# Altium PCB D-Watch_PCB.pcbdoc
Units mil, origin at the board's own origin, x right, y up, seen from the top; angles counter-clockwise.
Board outline 2207.1 x 1974.96 mil, 4 copper layers (Top Layer, Inner1, Inner2, Bottom Layer); 63 components, 57 nets, 260 pads, 83 vias.
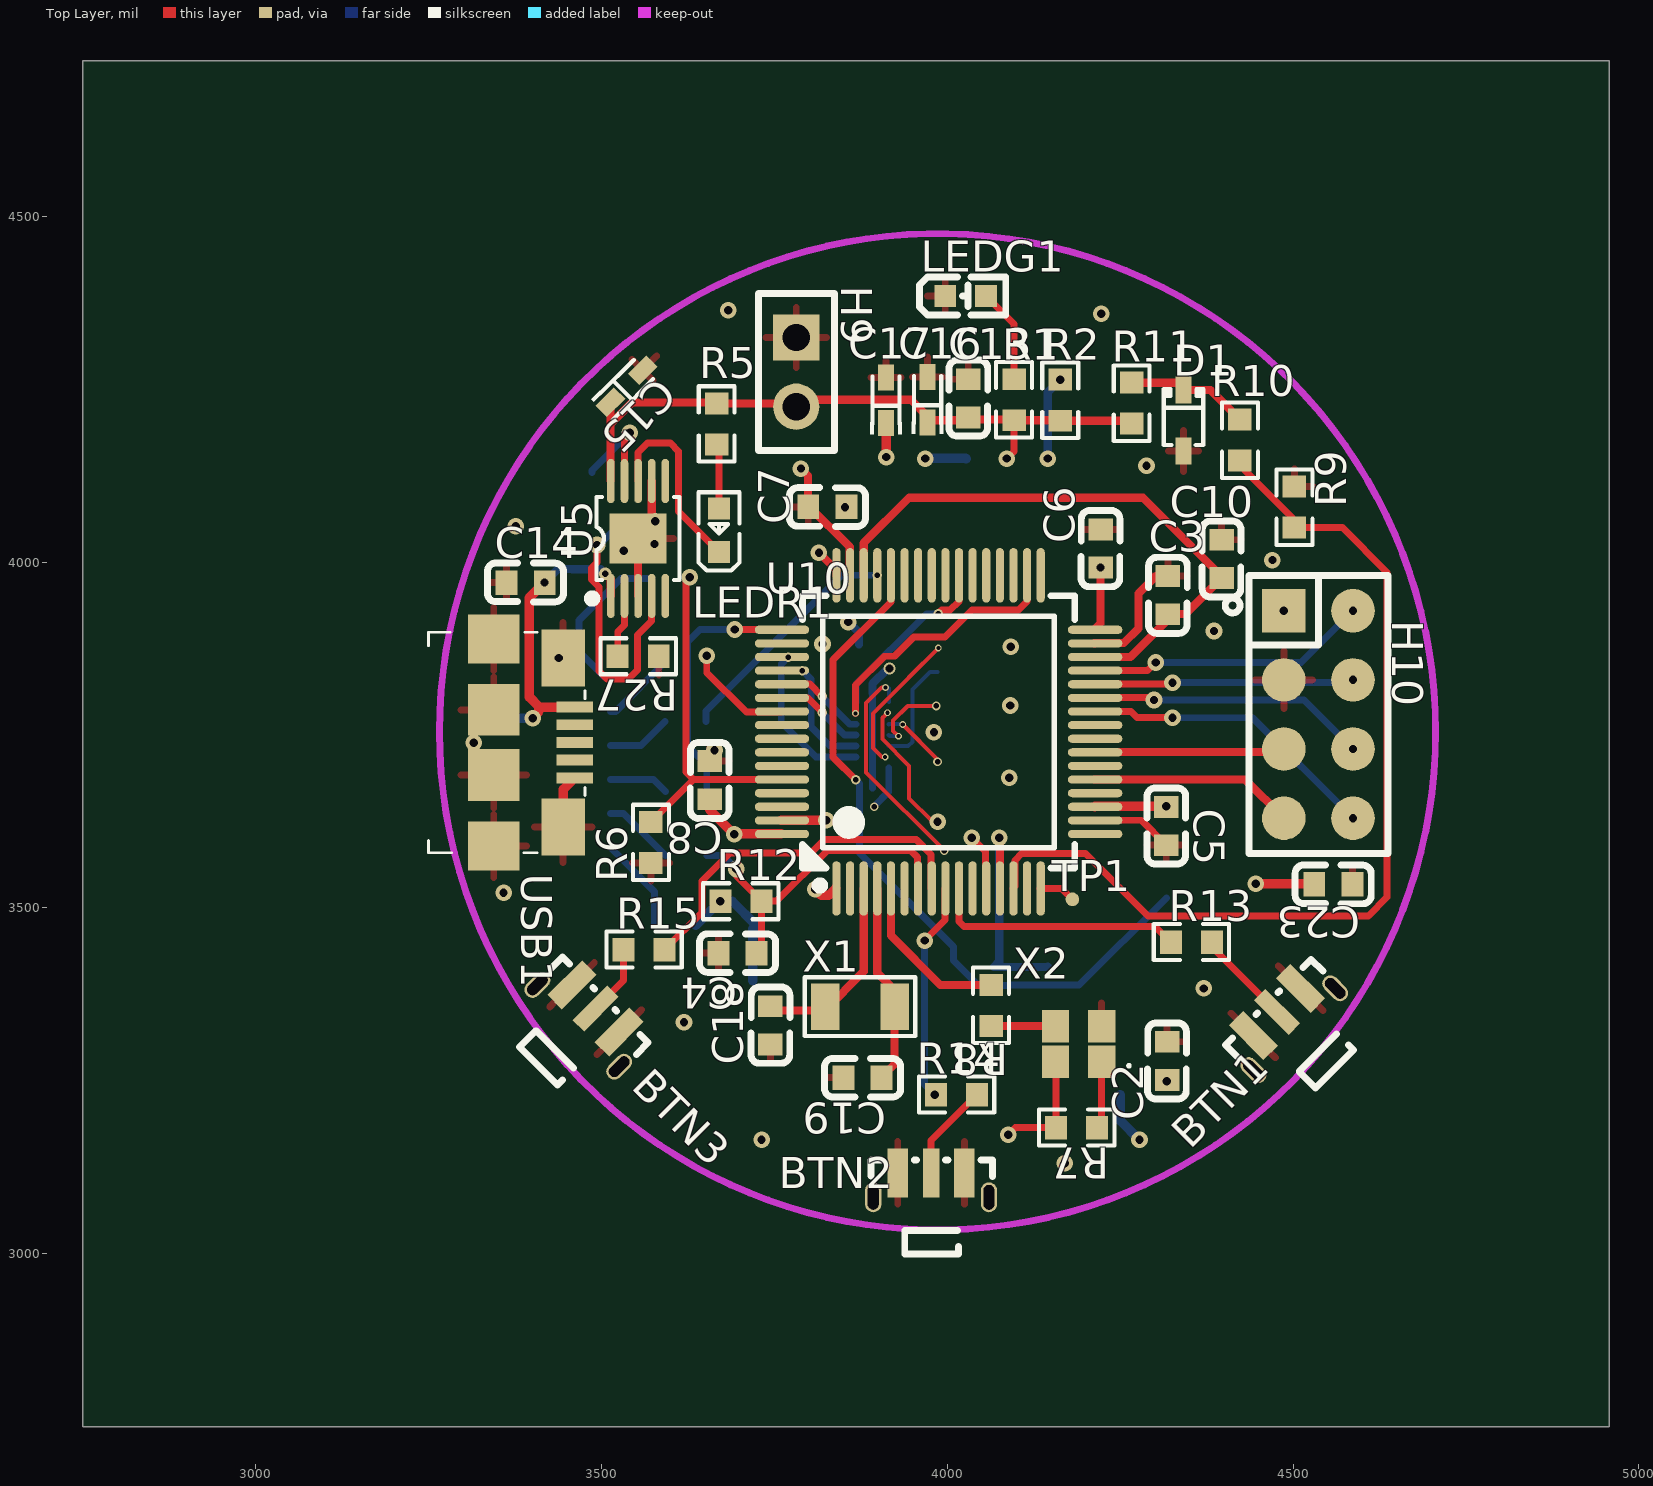
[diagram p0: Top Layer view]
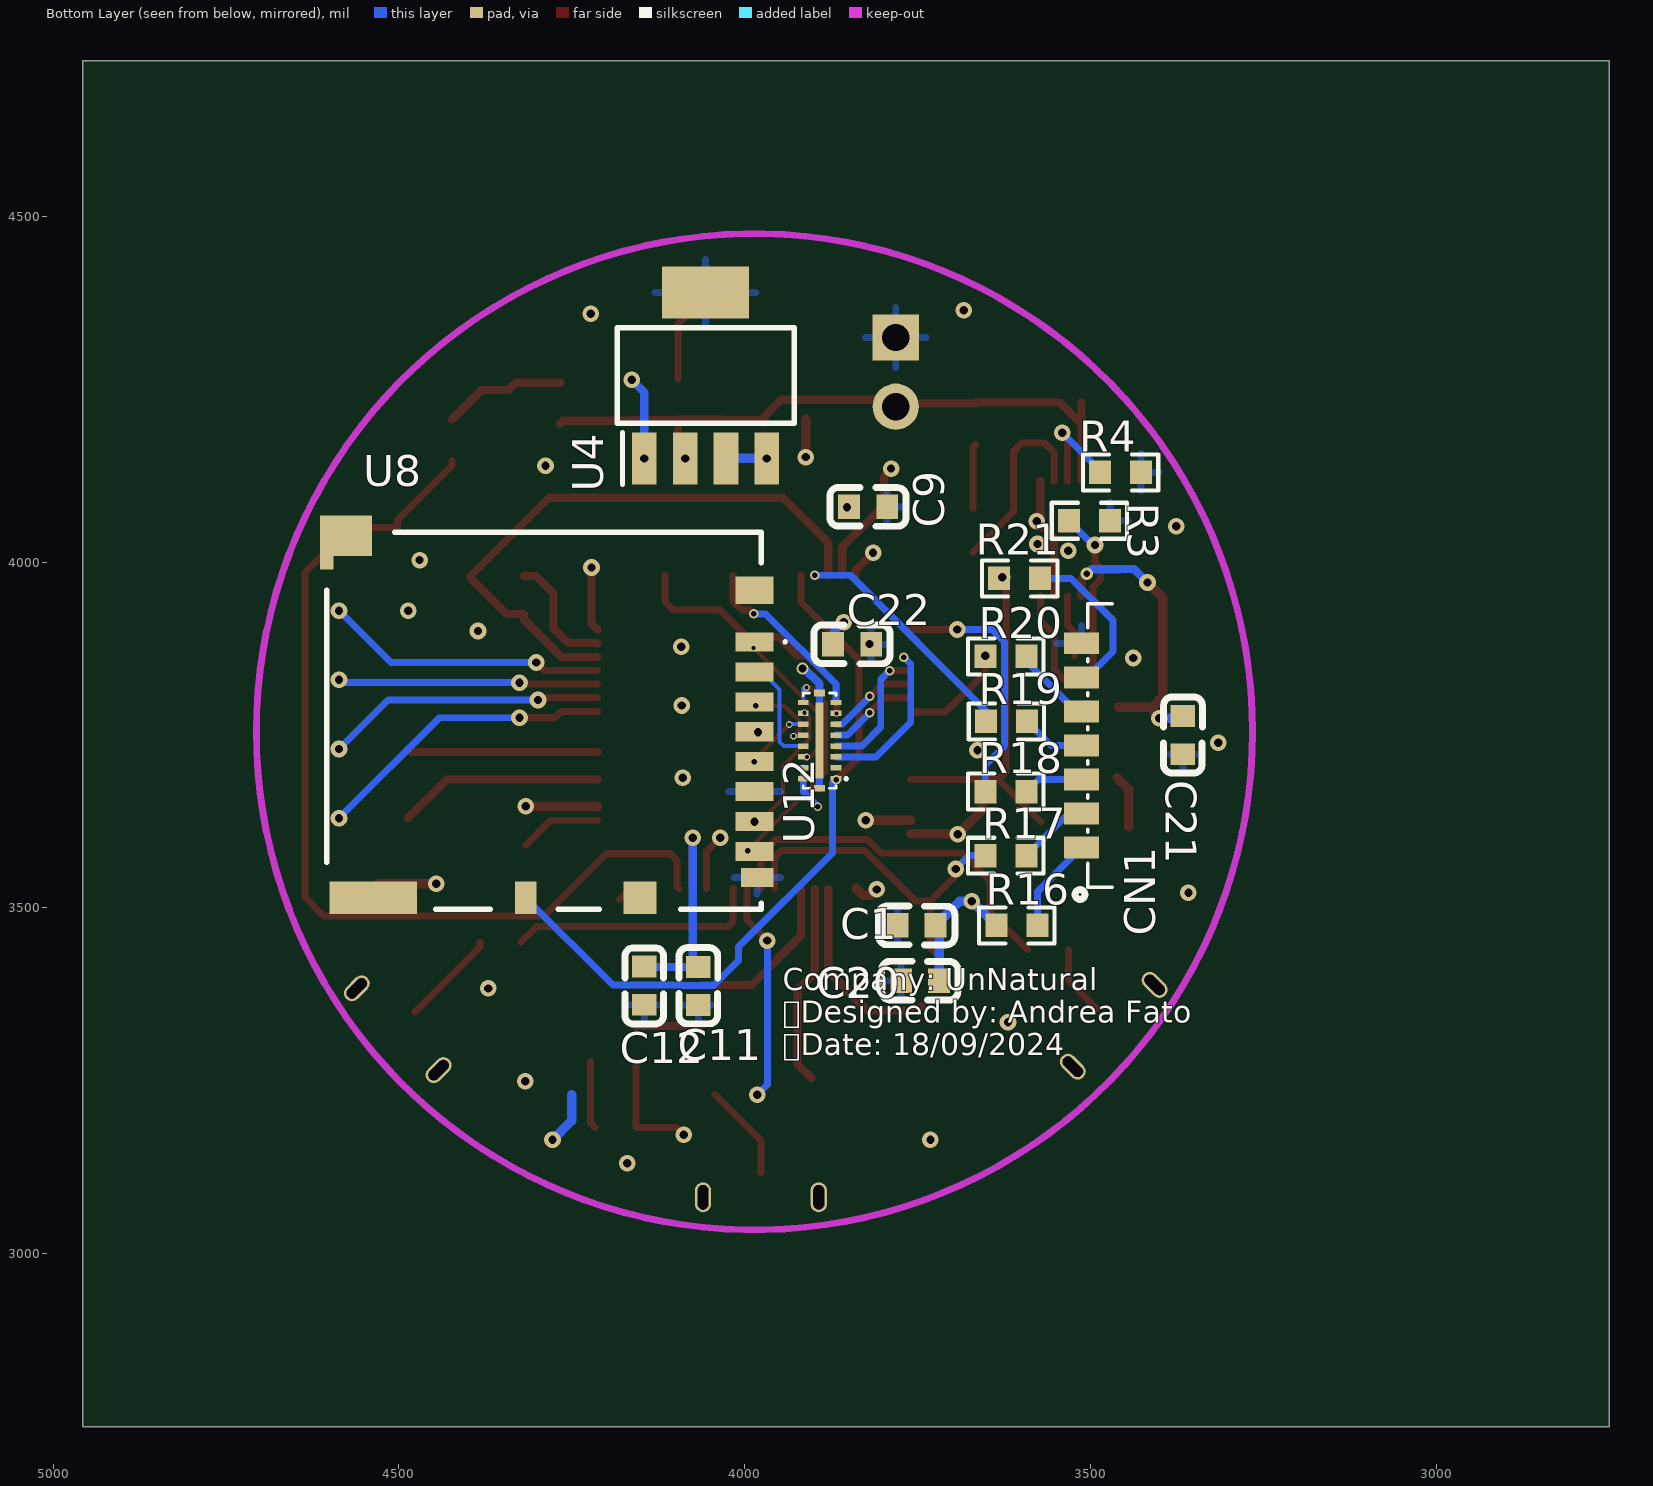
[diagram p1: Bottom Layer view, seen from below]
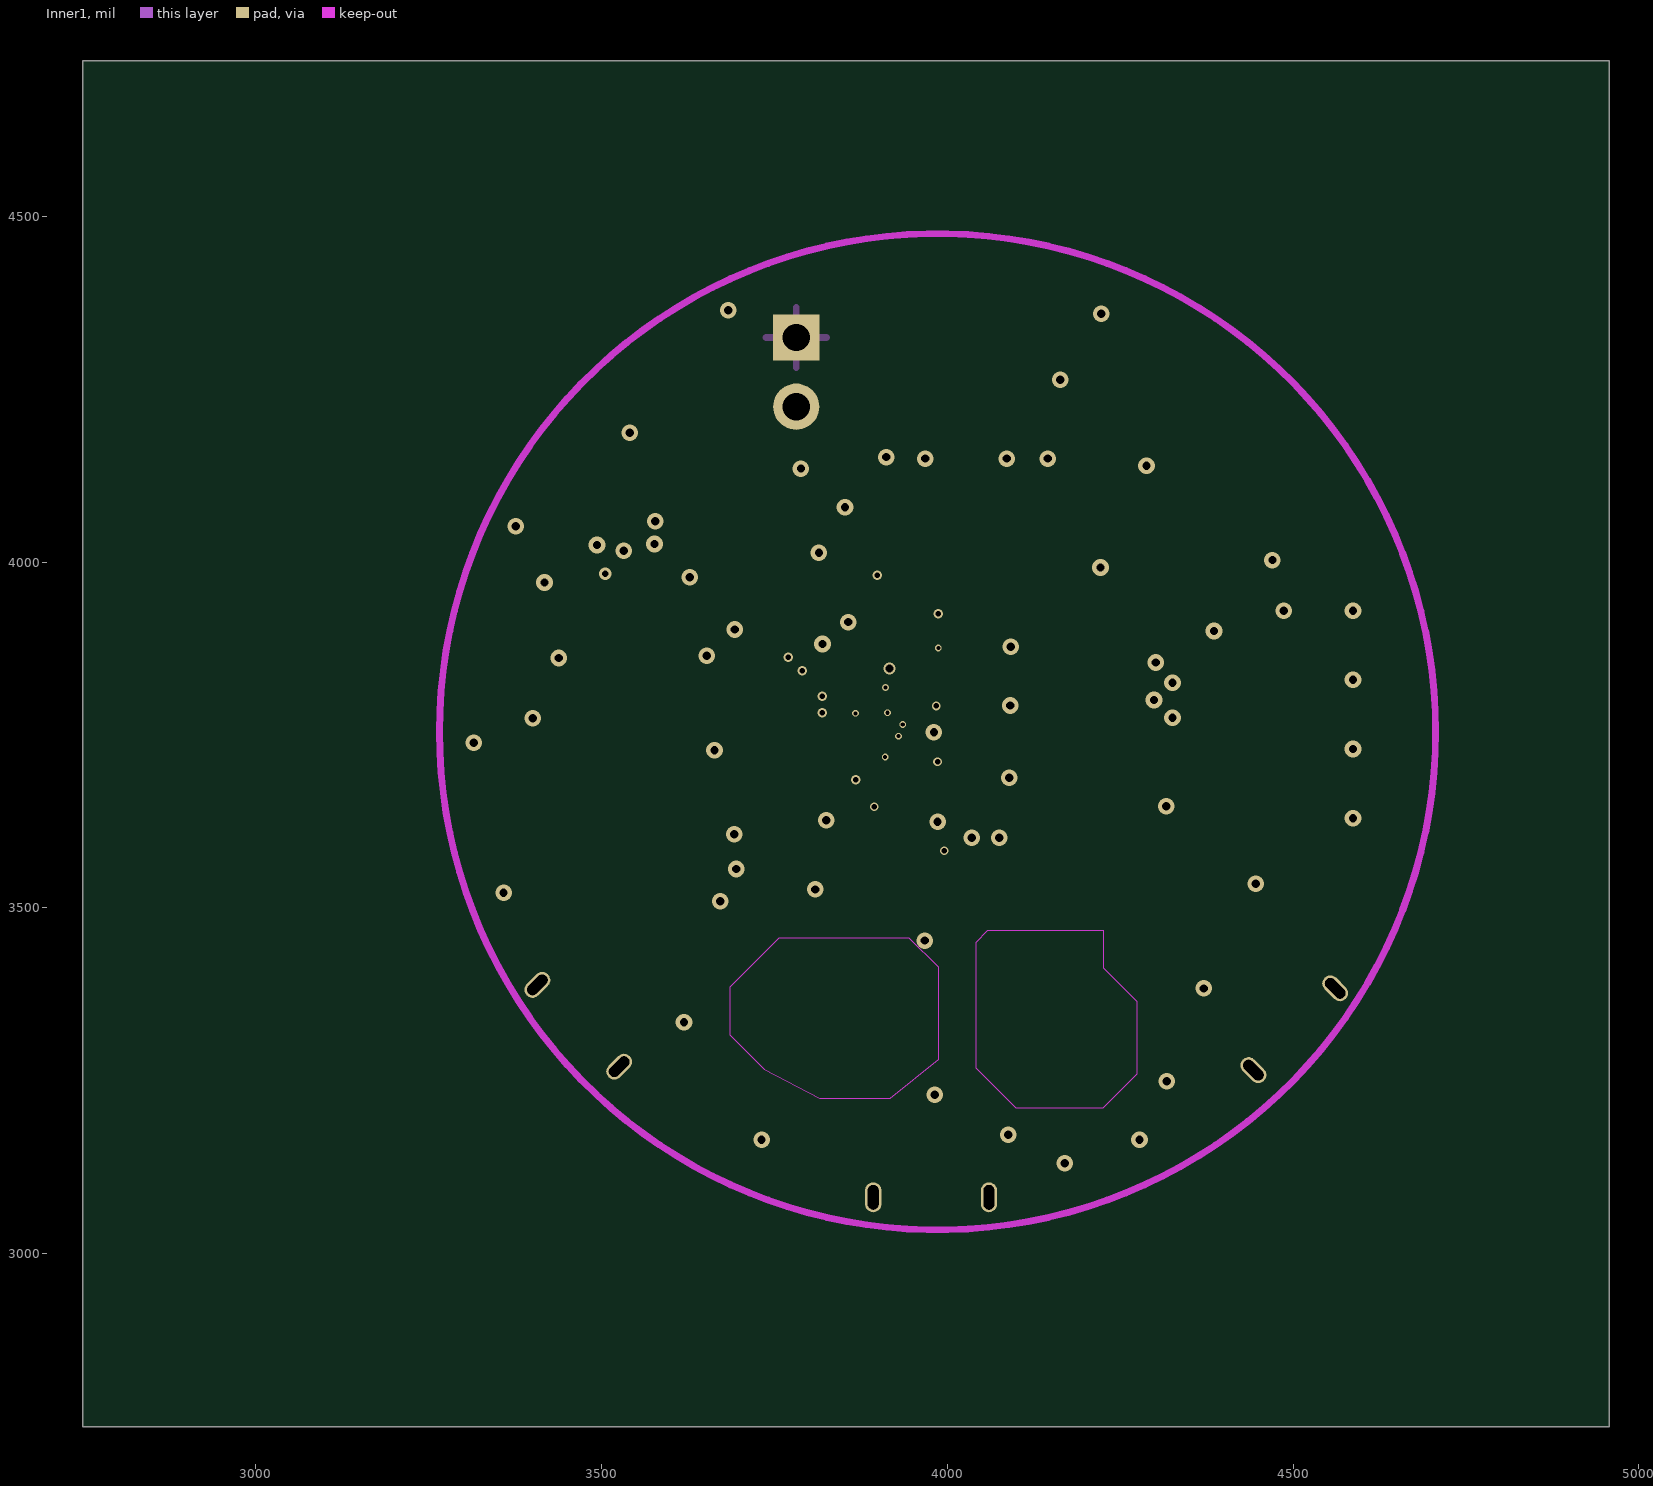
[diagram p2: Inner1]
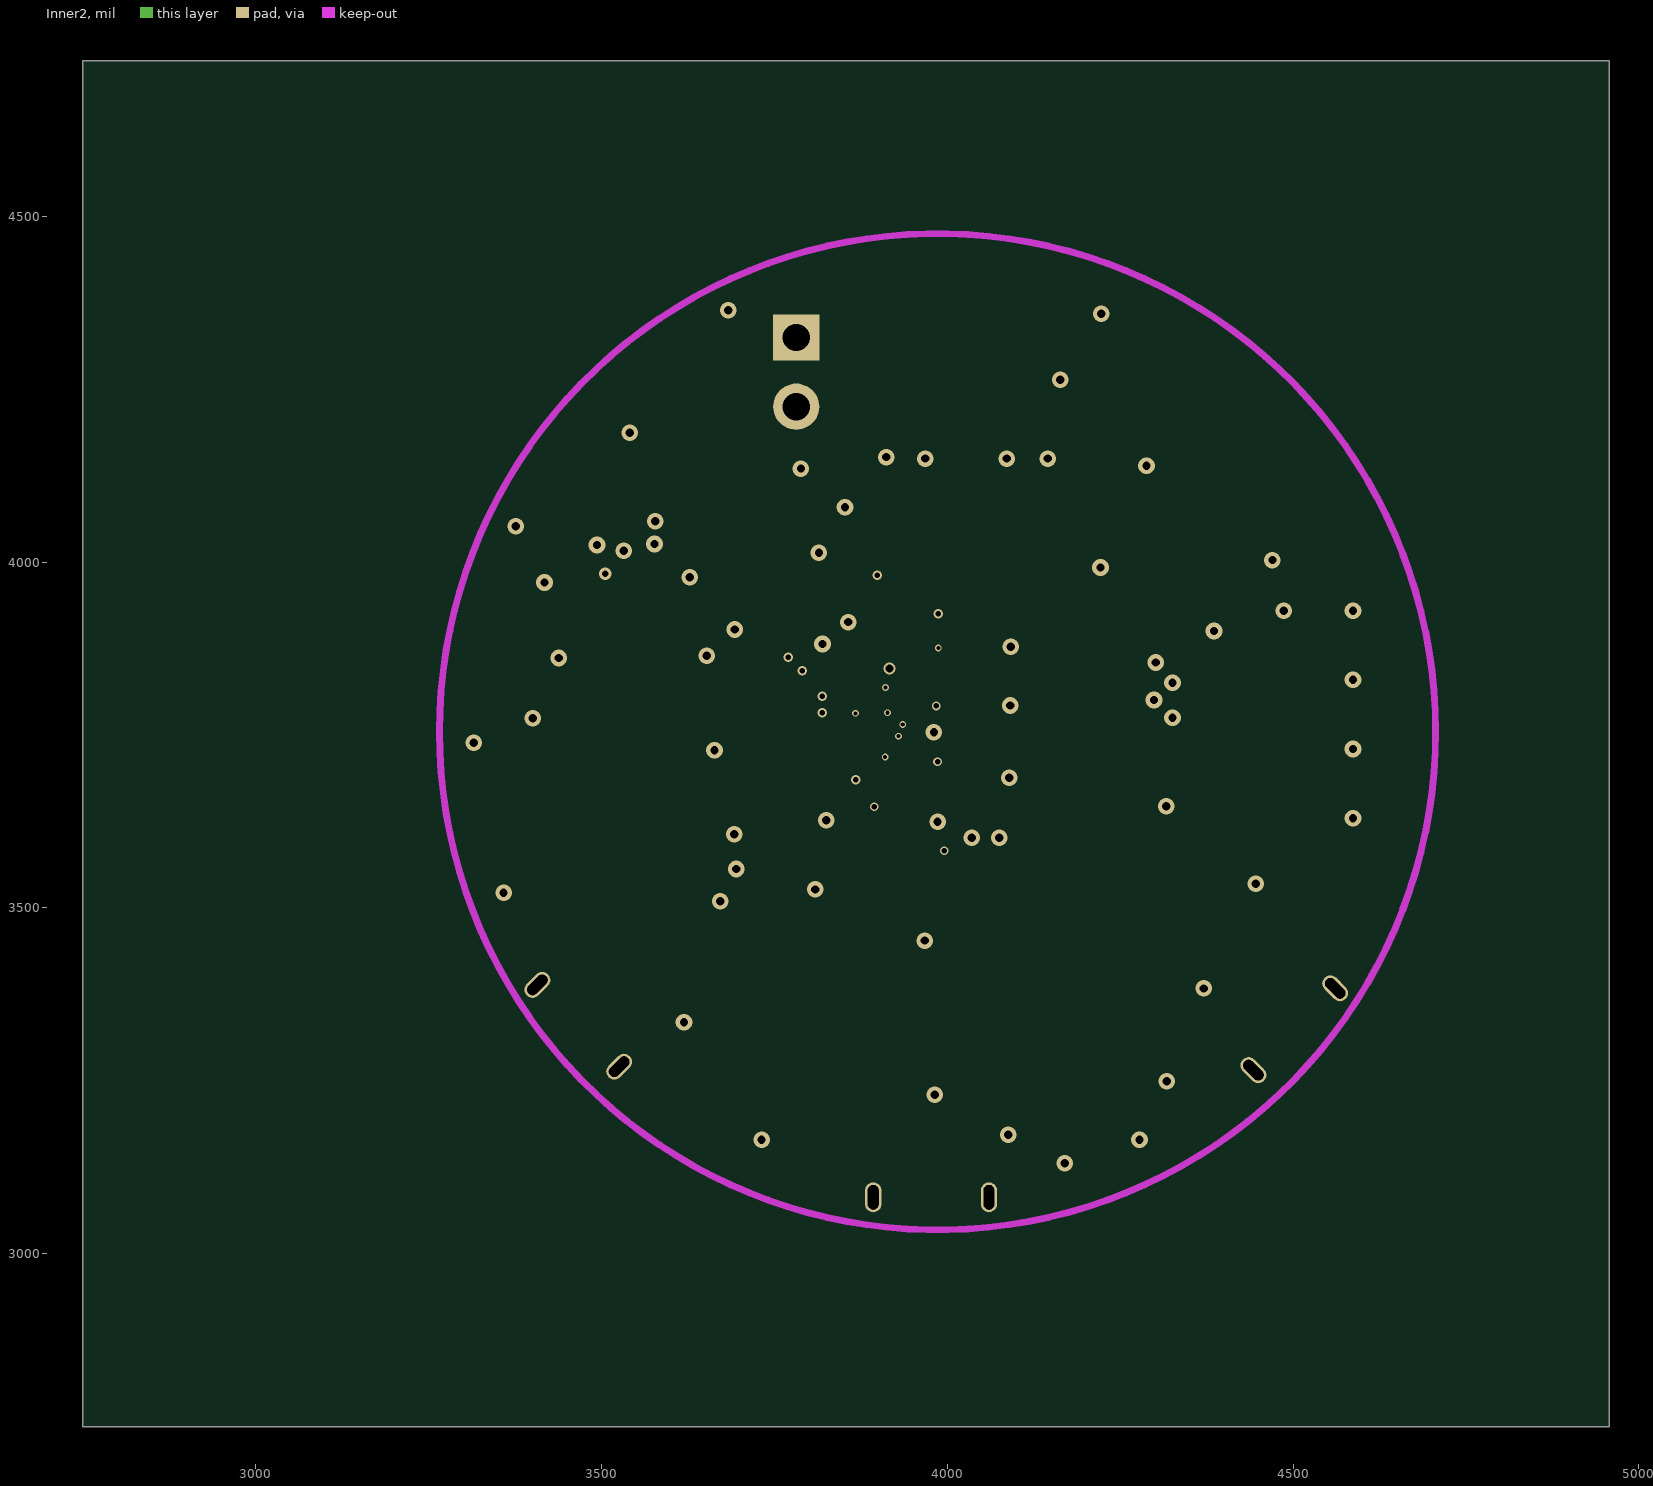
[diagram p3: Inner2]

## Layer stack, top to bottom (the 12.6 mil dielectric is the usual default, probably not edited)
Top Layer: signal copper (thickness not stored)
Dielectric: dielectric 12.6, FR-4, Dk 4.8
Inner1: signal copper (thickness not stored)
Dielectric: dielectric 12.6, FR-4, Dk 4.8
Inner2: signal copper (thickness not stored)
Dielectric: dielectric 12.6, FR-4, Dk 4.8
Bottom Layer: signal copper (thickness not stored)

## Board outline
4957.1,2750 2750,2750 2750,4724.96 4957.1,4724.96

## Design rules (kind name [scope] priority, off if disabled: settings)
Clearance copperThickness1oz [All] p1: gap=7 ignorepadtopadclearanceinfootprint=FALSE except(0.4: SMDPad-SMDPad; 4: Track-Track; 6: Track-SMDPad Track-THPad SMDPad-THPad THPad-THPad Track-Via SMDPad-Via THPad-Via Via-Via Track-Fill SMDPad-Fill THPad-Fill Via-Fill Fill-Fill SMDPad-Region THPad-Region Via-Region Fill-Region Region-Region Track-Poly SMDPad-Poly THPad-Poly Via-Poly Fill-Poly Poly-Poly Track-Text SMDPad-Text THPad-Text Via-Text Fill-Text Region-Text Poly-Text Text-Text; 6.9: Track-Hole SMDPad-Hole THPad-Hole Via-Hole Fill-Hole Region-Hole Poly-Hole Text-Hole Sheet-Hole; 11.8: Track-Region Region-Poly Track-Sheet SMDPad-Sheet THPad-Sheet Via-Sheet Fill-Sheet Region-Sheet Poly-Sheet Text-Sheet)
Clearance copperThickness2oz [All] p1: gap=7 ignorepadtopadclearanceinfootprint=FALSE except(6: Track-SMDPad SMDPad-SMDPad Track-THPad SMDPad-THPad THPad-THPad Track-Via SMDPad-Via THPad-Via Via-Via SMDPad-Fill THPad-Fill Via-Fill Fill-Fill Track-Region SMDPad-Region THPad-Region Via-Region Region-Region Track-Poly SMDPad-Poly THPad-Poly Via-Poly Fill-Poly Region-Poly Poly-Poly Track-Text SMDPad-Text THPad-Text Via-Text Fill-Text Region-Text Poly-Text Text-Text; 6.9: Track-Hole SMDPad-Hole THPad-Hole Via-Hole Fill-Hole Region-Hole Poly-Hole Text-Hole Sheet-Hole; 8: Track-Track; 11.8: Track-Fill Fill-Region Track-Sheet SMDPad-Sheet THPad-Sheet Via-Sheet Fill-Sheet Region-Sheet Poly-Sheet Text-Sheet)
Clearance BGA [All] p1: gap=7 ignorepadtopadclearanceinfootprint=FALSE except(3.9: Track-Track Track-SMDPad SMDPad-SMDPad Track-THPad SMDPad-THPad THPad-THPad Track-Via SMDPad-Via THPad-Via Via-Via Track-Fill SMDPad-Fill THPad-Fill Via-Fill Fill-Fill Track-Region SMDPad-Region THPad-Region Via-Region Fill-Region Region-Region Track-Poly SMDPad-Poly THPad-Poly Via-Poly Fill-Poly Region-Poly Poly-Poly Track-Hole SMDPad-Hole THPad-Hole Via-Hole Fill-Hole Region-Hole Poly-Hole Text-Hole Sheet-Hole; 6: Track-Text SMDPad-Text THPad-Text Via-Text Fill-Text Region-Text Poly-Text Text-Text; 11.8: Track-Sheet SMDPad-Sheet THPad-Sheet Via-Sheet Fill-Sheet Region-Sheet Poly-Sheet Text-Sheet)
DiffPairsRouting differentialPair [All] p1: maxuncoupledlength=10 maxlimit=5.9843 mostfreqgap=5.9843 toplayer_minwidth=5 toplayer_prefwidth=10 toplayer_maxwidth=100 bottomlayer_minwidth=5 bottomlayer_prefwidth=10 bottomlayer_maxwidth=100 midlayer1_minwidth=5 midlayer1_prefwidth=10 midlayer1_maxwidth=100 midlayer2_minwidth=5 midlayer2_prefwidth=10 midlayer2_maxwidth=100
PasteMaskExpansion pasteMaskExpansion [All] p1:
PlaneConnect innerPlane [All] p1: planeconnectstyle=Relief reliefexpansion=20 reliefentries=4 reliefconductorwidth=10 reliefairgap=10
PolygonConnect copperRegion [All] p1: connectstyle=Relief reliefentries=4 reliefconductorwidth=10 polygonreliefangle="90 Angle" airgapwidth=10
PolygonConnect copperRegionOSC [All] p1: connectstyle=Relief reliefentries=4 reliefconductorwidth=10 polygonreliefangle="90 Angle" airgapwidth=10
RoutingVias viaSize [All] p1: viastyle="Through Hole" holewidth=12.0078 minholewidth=5.9056 maxholewidth=248.0314 width=24.0158 minwidth=9.8426 maxwidth=393.7008
SolderMaskExpansion solderMaskExpansion [All] p1: useseparateexpansions=TRUE expansion=2.0079 expansionbottom=2.0079
Width copperThickness1oz [All] p1: maxlimit=100 minlimit=4 preferedwidth=10
Width copperThickness2oz [All] p1: maxlimit=100 minlimit=8 preferedwidth=10

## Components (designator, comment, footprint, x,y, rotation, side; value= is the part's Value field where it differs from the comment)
BTN1 "436333033816" SW-SMD_436333033816 4506.58,3319.8 r45 top
BTN2 "436333033816" SW-SMD_436333033816 3976.58,3074.8 r0 top
BTN3 "436333033816" SW-SMD_436333033816 3461.58,3324.8 r315 top
C1 "GCJ188R71C104KA01D" C0603 3751.58,3474.8 r0 bottom
C2 "GCJ188R71C104KA01D" C0603 4317.72,3278.97 r90 top
C3 "GCJ188R71C104KA01D" C0603 4319.02,3952.36 r90 top
C4 "GCJ188R71C104KA01D" C0603 3696.58,3434.8 r180 top
C5 "GCJ188R71C104KA01D" C0603 4316.54,3618.34 r270 top
C6 "GCJ188R71C104KA01D" C0603 4221.58,4019.8 r90 top
C7 "GCJ188R71C104KA01D" C0603 3826.58,4079.8 r180 top
C8 "GCJ188R71C104KA01D" C0603 3656.58,3684.8 r90 top
C9 "GCJ188C70J475KE02D" C0603 3821.58,4079.8 r180 bottom
C10 "GCJ188R71C104KA01D" C0603 4396.58,4004.8 r90 top
C11 "GCJ188R71C104KA01D" C0603 4067.17,3387.28 r270 bottom
C12 "CC0603KRX7R5BB105" C0603 4145.12,3387.68 r90 bottom
C13 "CC0603KRX7R5BB105" C0603 4030.32,4236.84 r270 top
C14 "CC0603KRX7R5BB105" C0603 3390.4,3970.55 r0 top
C15 "T58MM106M6R3C0300" CAP-SMD_L1.6-W0.8-RD 3536.22,4254.17 r225 top
C16 "T58MM106M6R3C0300" CAP-SMD_L1.6-W0.8-RD 3971.58,4234.8 r270 top
C17 "T58MM106M6R3C0300" CAP-SMD_L1.6-W0.8-RD 3911.42,4234.09 r270 top
C18 "CAP_0603" C0603 3744.24,3330.27 r270 top
C19 "CAP_0603" C0603 3877.31,3254.65 r180 top
C20 "AC0603KRX7R6BB105" C0603 3746.58,3394.8 r180 bottom
C21 "GCJ188R71C104KA01D" C0603 3366.58,3749.8 r270 bottom
C22 "GCJ188R71C104KA01D" C0603 3844.69,3881.06 r180 bottom
C23 "GCJ188R71C104KA01D" C0603 4558.23,3534.02 r0 top
CN1 "53398-0771" CONN-SMD_7P-P1.25_53398-0771 3458.87,3734.99 r90 bottom
D1 "TDZ3V6J,115" SOD-323_L1.7-W1.3-LS2.5-RD-1 4341.58,4204.8 r270 top
H9 "HDR-F_2.54_1x2P" HDR-TH_2P-P2.54-V-F 3781.58,4274.8 r270 top
H10 "HDR-F-2.54_2x4" HDR-TH_8P-P2.54-V-F-R2-C4-S2.54-1 4536.58,3779.8 r270 top
LEDG1 "APT1608MGC" LED-SMD_L1.6-W0.8-RD 4026.58,4384.8 r0 top
LEDR1 "APT1608SURCK" LED0603-RD 3670.11,4046.28 r90 top
R1 "Res_0603" R0603 4096.58,4234.8 r270 top
R2 "Res_0603" R0603 4163.39,4234.09 r90 top
R3 "Res_0603" R0603 3501.58,4059.8 r0 bottom
R4 "Res_0603" R0603 3456.58,4129.8 r180 bottom
R5 "Res_0603" R0603 3666.58,4199.8 r270 top
R6 "Res_0603" R0603 3571.58,3594.8 r90 top
R7 "Res_0603" R0603 4187.01,3182.39 r180 top
R8 "Res_0603" R0603 4063.25,3359.15 r90 top
R9 "Res_0603" R0603 4501.92,4079.46 r90 top
R10 "Res_0603" R0603 4423.1,4176.43 r90 top
R11 "Res_0603" R0603 4266.58,4229.8 r270 top
R12 "Res_0603" R0603 3701.58,3509.8 r0 top
R13 "Res_0603" R0603 4352.99,3450.75 r180 top
R14 "Res_0603" R0603 4013.39,3230.15 r180 top
R15 "Res_0603" R0603 3561.58,3439.8 r0 top
R16 "Res_0603" R0603 3606.58,3474.8 r180 bottom
R17 "Res_0603" R0603 3622.52,3575.61 r180 bottom
R18 "Res_0603" R0603 3622.52,3668.31 r180 bottom
R19 "Res_0603" R0603 3621.58,3769.8 r180 bottom
R20 "Res_0603" R0603 3622.52,3863.71 r180 bottom
R21 "Res_0603" R0603 3602.52,3976.41 r180 bottom
R27 "Res_0603" R0603 3553.15,3864.01 r180 top
TP1 "Test-Point" Test-Point-0.5mm 4180.85,3512.51 r0 top
U4 "LP3874EMP-3.3_NOPB_" SOT150P700X180-5N 4056.58,4269.8 r90 bottom
U5 "BQ24092DGQR" MSOP-10_L3.0-W3.0-P0.50-LS5.0-BL-EP 3552.91,4034.22 r0 top
U8 "DM3BT-DSF-PEJS_" DM3BTDSFPEJS 4286.17,3779.4 r270 bottom
U10 "STM32H7B0RBT6" LQFP-64_L10.0-W10.0-P0.50-LS12.0-BL 3987.4,3754.56 r0 top
U12 "EMIF06-MSD02N16" QFN-16L_L3.5-W1.2-P0.40_EMIF06-MSD02N16 3891.73,3741.96 r90 bottom
USB1 "10118192-0001LF" MICRO-USB-SMD_10118192-0001LF_1 3402.83,3739.33 r270 top
X1 "NX3215SA-32.768K-STD-MUA-9" CRYSTAL-SMD_L3.2-W1.5-1 3873.84,3357.36 r0 top
X2 "EC5625ETTTS-25.000M_TR_" EC5625ETTTS25000MTR 4189.76,3303.38 r180 top

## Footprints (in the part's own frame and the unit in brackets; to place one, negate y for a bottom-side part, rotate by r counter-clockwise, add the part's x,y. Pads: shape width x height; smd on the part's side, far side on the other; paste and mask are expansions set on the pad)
C0603 [mm]
  rect 0.8x0.9 smd: 1(-0.7,0) 2(0.7,0)
  silkscreen extent -1.41,-0.71 1.39,0.72
CAP-SMD_L1.6-W0.8-RD [mil]
  rect 37.57x23.39 smd: 1(32.86,0) 2(-32.86,0)
  silkscreen extent -34,-23 49,23
CONN-SMD_7P-P1.25_53398-0771 [mm]
  rect 0.8x1.3 smd: 1(-3.75,1.375) 2(-2.5,1.375) 3(-1.25,1.375) 4(0,1.375) 5(1.25,1.375) 6(2.5,1.375) 7(3.75,1.375)
  silkscreen extent -5.65,0.25 5.21,1.61
CRYSTAL-SMD_L3.2-W1.5-1 [mm]
  rect 1.05x1.7 smd: 1(-1.275,0) 2(1.275,0)
  silkscreen extent -2.03,-1.08 2.03,1.08
DM3BTDSFPEJS [mm]
  rect 0.7x1.4 smd: 1(-2.675,7.625) 2(-1.575,7.625) 3(-0.475,7.625) 4(0.625,7.625) 5(1.725,7.625) 6(2.825,7.625) 7(3.925,7.625) 8(5.025,7.625)
  rect 1.2x0.8 smd: 9(6.725,-0.775)
  rect 0.7x1.2 smd: 10(5.975,7.725)
  rect 1x1.4 smd: 11(-4.575,7.625)
  rect 1.2x1.2 smd: 12(6.725,3.425)
  rect 1.2x3.2 smd: 13(6.725,-6.375)
  rect 1.5x1.9 smd: 14(-6.575,-7.375)
  rect 0.5x0.5 smd: 15(-5.575,-8.075)
  silkscreen extent -6.7,-8.07 7.15,8.8
EC5625ETTTS25000MTR [mm]
  rect 1x1.2 smd: 1(-0.85,0.65) 2(-0.85,-0.65) 3(0.85,-0.65) 4(0.85,0.65)
  silkscreen extent -1.9,0.75 -1.8,0.85
HDR-TH_2P-P2.54-V-F [mm]
  rect 1.7x1.7 hole 1: 1(-1.27,0)
  round 1.7 hole 1: 2(1.27,0)
  silkscreen extent -2.88,-1.39 2.88,1.4
HDR-TH_8P-P2.54-V-F-R2-C4-S2.54-1 [mm]
  rect 1.6x1.6 smd: 1(-3.81,-1.27)
  round 1.6 smd: 2(-3.81,1.27) 3(-1.27,-1.27) 4(-1.27,1.27) 5(1.27,-1.27) 6(1.27,1.27) 7(3.81,-1.27) 8(3.81,1.27)
  silkscreen extent -5.1,-3.42 5.1,2.55
LED0603-RD [mm]
  rect 0.8x0.8 smd: 1(-0.799,0) 2(0.799,0)
  silkscreen extent -1.49,-0.75 1.39,0.76
LED-SMD_L1.6-W0.8-RD [mm]
  rect 0.8x0.8 smd: 1(-0.75,0) 2(0.75,0)
  silkscreen extent -1.7,-0.7 1.47,0.7
LQFP-64_L10.0-W10.0-P0.50-LS12.0-BL [mm]
  oval 0.3x2 smd: 1(-3.75,-5.75) 2(-3.25,-5.75) 3(-2.75,-5.75) 4(-2.25,-5.75) 5(-1.75,-5.75) 6(-1.25,-5.75) 7(-0.75,-5.75) 8(-0.25,-5.75) 9(0.25,-5.75) 10(0.75,-5.75) 11(1.25,-5.75) 12(1.75,-5.75) 13(2.25,-5.75) 14(2.75,-5.75) 15(3.25,-5.75) 16(3.75,-5.75) 33(3.75,5.75) 34(3.25,5.75) 35(2.75,5.75) 36(2.25,5.75) 37(1.75,5.75) 38(1.25,5.75) 39(0.75,5.75) 40(0.25,5.75) 41(-0.25,5.75) 42(-0.75,5.75) 43(-1.25,5.75) 44(-1.75,5.75) 45(-2.25,5.75) 46(-2.75,5.75) 47(-3.25,5.75) 48(-3.75,5.75)
  oval 2x0.3 smd: 17(5.75,-3.75) 18(5.75,-3.25) 19(5.75,-2.75) 20(5.75,-2.25) 21(5.75,-1.75) 22(5.75,-1.25) 23(5.75,-0.75) 24(5.75,-0.25) 25(5.75,0.25) 26(5.75,0.75) 27(5.75,1.25) 28(5.75,1.75) 29(5.75,2.25) 30(5.75,2.75) 31(5.75,3.25) 32(5.75,3.75) 49(-5.75,3.75) 50(-5.75,3.25) 51(-5.75,2.75) 52(-5.75,2.25) 53(-5.75,1.75) 54(-5.75,1.25) 55(-5.75,0.75) 56(-5.75,0.25) 57(-5.75,-0.25) 58(-5.75,-0.75) 59(-5.75,-1.25) 60(-5.75,-1.75) 61(-5.75,-2.25) 62(-5.75,-2.75) 63(-5.75,-3.25) 64(-5.75,-3.75)
  silkscreen extent -5,-5.79 5,5
MICRO-USB-SMD_10118192-0001LF_1 [mm]
  rect 0.4x1.35 smd: 1(-1.3,1.487) 2(-0.65,1.487) 3(0,1.487) 4(0.65,1.487) 5(1.3,1.487)
  rect 1.8x1.9 smd: 6(-3.8,-1.487) 6(3.8,-1.487)
  rect 2.1x1.6 smd: 6(-3.1,1.063) 6(3.1,1.063)
  rect 1.9x1.9 smd: 6(-1.199,-1.487) 6(1.199,-1.487)
  silkscreen extent -4.05,-3.89 4.05,1.86
MSOP-10_L3.0-W3.0-P0.50-LS5.0-BL-EP [mm]
  oval 0.28x1.62 smd: 1(-1,-2.11) 2(-0.5,-2.11) 3(0,-2.11) 4(0.5,-2.11) 5(1,-2.11) 6(1,2.11) 7(0.5,2.11) 8(0,2.11) 9(-0.5,2.11) 10(-1,2.11)
  rect 2.1x1.83 smd: 11(0,0)
  silkscreen extent -1.84,-2.35 1.52,1.52
QFN-16L_L3.5-W1.2-P0.40_EMIF06-MSD02N16 [mm]
  rect 0.2x0.4 smd: 1(-1.4,-0.6) 2(-1,-0.6) 3(-0.6,-0.6) 4(-0.2,-0.6) 5(0.2,-0.6) 6(0.6,-0.6) 7(1,-0.6) 8(1.4,-0.6) 10(1.4,0.6) 11(1,0.6) 12(0.6,0.6) 13(0.2,0.6) 14(-0.2,0.6) 15(-0.6,0.6) 16(-1,0.6) 17(-1.4,0.6)
  rect 0.25x0.4 smd: 9(1.75,0) 18(-1.75,0)
  rect 2.8x0.3 smd: 19(0,0)
  silkscreen extent -1.75,-1.02 1.75,0.6
R0603 [mil]
  rect 31.75x34.02 smd: 1(-29.66,0) 2(29.66,0)
  silkscreen extent -55,-26 55,26
SOD-323_L1.7-W1.3-LS2.5-RD-1 [mm]
  rect 0.985x0.6 smd: 1(-1.118,0) 2(1.118,0)
  silkscreen extent -1.15,-0.73 0.9,0.73
SOT150P700X180-5N [mm]
  rect 1.9x0.9 smd: 1(-3.05,2.25) 2(-3.05,0.75) 3(-3.05,-0.75) 4(-3.05,-2.25)
  rect 1.9x3.2 smd: 5(3.05,0)
  silkscreen extent -4,-3.25 1.75,3.25
SW-SMD_436333033816 [mm]
  rect 0.75x1.8 smd: 1(-1.225,1.075) 3(1.225,1.075)
  rect 0.6x1.8 smd: 2(0,1.075)
  oval 0.6x1.1 hole 0.4 slot 0.9 at 90 deg: 6(-2.125,0.175) 6(2.125,0.175)
  silkscreen extent -2.2,-1.9 2.25,1.55
Test-Point-0.5mm [mm]
  round 0.5 smd: 1(0,0)

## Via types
v1: diameter 24.02, hole 12.01, Top Layer to Bottom Layer, 63 vias
v2: diameter 13.78, hole 7.87, Top Layer to Bottom Layer, 7 vias
v3: diameter 9.84, hole 5.91, Top Layer to Bottom Layer, 7 vias
v4: diameter 12.6, hole 7.87, Top Layer to Bottom Layer, 4 vias
v5: diameter 17.72, hole 9.84, Top Layer to Bottom Layer, 1 vias
v6: diameter 17.72, hole 11.81, Top Layer to Bottom Layer, 1 vias

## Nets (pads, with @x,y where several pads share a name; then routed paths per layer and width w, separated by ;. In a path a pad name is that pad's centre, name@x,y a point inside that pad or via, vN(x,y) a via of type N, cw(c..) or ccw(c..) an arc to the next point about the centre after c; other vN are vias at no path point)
5V_USB_CHGR: C14.2 C21.1 U5.1 USB1.1 | length 435
  Top Layer w11.81: v5(3505.42,3983.35) 3513.54,3975.23 U5.1
  Top Layer w13.78: v1(3400.83,3774.21) 3400.83,3775.47 3409.64,3784.28 3409.64,3790.98 ; v1(3417.57,3970.55) 3395.67,3948.66 3395.67,3804.95 3409.64,3790.98 ; USB1.1@3459.43,3790.98 3458.96,3790.51 3410.12,3790.51 3409.64,3790.98
  Bottom Layer w11.81: v1(3417.57,3970.55) 3437.2,3990.18 3457.37,3990.18 3457.84,3989.72 3499.05,3989.72 v5(3505.42,3983.35)
  Bottom Layer w13.78: C21.1 3369.73,3774.21 v1(3400.83,3774.21)
$1N5489: R2.2 U4.1 | length 121.6
  Bottom Layer w11.81: v1(4145.16,4149.72) 4145.16,4245.52 v1(4163.39,4263.75)
$1N5967: R3.2 U5.4 | length 423.6
  Top Layer w10: v1(3493.58,4024.8) 3493.58,3999.57 3485.58,3991.57 3485.58,3975.13 3496.63,3964.08 3496.63,3842.45 3508.14,3830.94 3538.84,3830.94 3552.13,3844.23 3552.13,3894.49 3572.44,3914.8 3572.44,3950.99 U5.4
  Bottom Layer w10: v1(3493.58,4024.8) 3496.24,4024.8 R3.2
$1N5968: R27.2 U5.2 | length 91.2
  Top Layer w10: R27.2 3523.49,3899.31 3533.23,3909.05 U5.2
$1N5969: R4.1 U5.9 | length 153.4
  Top Layer w10: U5.9 3533.23,4179.37 v1(3541.1,4187.24)
  Bottom Layer w10: R4.1 3486.24,4132.38 v1(3541.1,4187.24)
$1N5973: LEDR1.1 U5.8 | length 280.4
  Top Layer w10: U5.8 3552.91,4158.65 3566.54,4172.28 3599.61,4172.28 3611.59,4160.29 3611.59,4073.31 LEDR1.1
$1N5974: LEDR1.2 R5.2 | length 93.9
  Top Layer w10: R5.2 3670.11,4166.62 LEDR1.2
$1N6463: LEDG1.2 R1.1 | length 137.1
  Top Layer w10: LEDG1.2 4096.58,4344.33 R1.1
$2N8217: R7.1 X2.1 | length 98.1
  Top Layer w10: R7.1 4223.23,3188.95 X2.1
$2N8264: R8.1 X2.3 | length 93.3
  Top Layer w11.81: R8.1 4155.78,3329.49 X2.3
$2N18890: D1.1 R10.2 R11.1 | length 178.6
  Top Layer w11.81: R11.1 4330.92,4259.46 D1.1 4380.39,4248.8 R10.2
$2N23973: TP1.1 U10.16 | length 53.2
  Top Layer w10: U10.16@4134.22,3528.43 4164.93,3528.43 TP1.1
$3N1058: CN1.1 R16.2 | length 139
  Bottom Layer w10: CN1.1 3576.92,3523.44 R16.2
$3N1061: CN1.2 R17.2 | length 105.1
  Bottom Layer w10: CN1.2 3531.91,3636.56 R17.2
$3N1065: CN1.3 R18.2 | length 87.1
  Bottom Layer w10: CN1.3 3575.39,3685.78 R18.2
$3N1094: CN1.4 R19.2 | length 93.3
  Bottom Layer w10: CN1.4 3557.11,3734.99 R19.2
$3N1097: CN1.5 R20.2 | length 117.1
  Bottom Layer w10: CN1.5 3520.66,3784.2 3592.86,3856.39 R20.2
$3N1126: CN1.6 R21.2 | length 236
  Bottom Layer w10: CN1.6 3505.35,3833.41 3467.72,3871.04 3467.72,3915.98 3528.16,3976.41 R21.2
$3N2256: BTN2.2 R14.1 | length 140.6
  Top Layer w10: BTN2.2 3976.58,3163.69 R14.1
$3N2358: BTN3.2 R15.1 | length 101.8
  Top Layer w10: BTN3.2 3531.92,3395.14 R15.1
$3N11256: BTN1.2 R13.1 | length 140
  Top Layer w10: R13.1 4382.65,3443.74 BTN1.2
$3N14921: U8.1 U12.15 | length 206.2
  Top Layer w5.91: v3(3910.24,3718.5) 3905.75,3718.5 3892.68,3731.57 3892.68,3781.38 3944.1,3832.8 ; 3944.1,3832.88 v3(3987.01,3875.8)
$3N14926: U8.3 U12.13 | length 111.4
  Top Layer w5.91: v3(3929.42,3748.34) 3921.76,3756 3921.76,3770.96 3942.82,3792.08 v4(3983.93,3792.08)
  Bottom Layer w5.91: U12.13 3916.85,3748.34 v3(3929.42,3748.34)
$3N14931: U8.2 U12.14 | length 159.2
  Bottom Layer w5.91: U12.14 3943.31,3734.09 3949.48,3740.26 3949.48,3815.58 3975.31,3841.4 U8.2
$3N15872: U8.7 U12.11 | length 197.1
  Top Layer w5.91: v3(3913.38,3782.24) 3906.11,3774.97 3906.11,3744.1 3944.88,3705.32 3944.88,3658.5 3977.17,3626.21 v1@3985.83,3626.21
  other v1: 3985.98,3624.87
$3N15878: U8.8 U12.10 | length 322
  Top Layer w5.91: v3(3910.51,3818.82) 3905.2,3818.82 3882.76,3796.37 3882.76,3695.82 v4(3995.67,3582.91)
  Bottom Layer w5.91: v3(3910.51,3818.82) 3913.7,3818.82 3915.48,3817.04 U12.10@3915.48,3798.01
$3N16235: U8.5 U12.12 | length 95.2
  Top Layer w5.91: v3(3935.62,3765.22) 3985.98,3714.87 v4(3985.98,3711.48)
  Bottom Layer w5.91: U12.12 3915.53,3765.76 3935.09,3765.76 v3(3935.62,3765.22)
+3V3: 
ADC1_IN16: R9.1 R10.1 U10.14 | length 1392.5
  Top Layer w10: U10.14@4094.85,3528.43 4097.64,3531.22 4097.64,3568.89 4107.53,3578.79 4199.79,3578.79 4290.16,3488.42 4608.66,3488.42 4635.8,3515.56 4635.8,3985.3 4571.29,4049.8 R9.1 4501.92,4060.71 4423.1,4139.52 R10.1
BOOT0: R6.2 R21.1 U10.60 | length 513.3
  Top Layer w10: R6.2 3633.02,3685.9 ; v1(3627.72,3977.99) 3622.05,3972.32 3622.05,3696.87 3633.02,3685.9 ; U10.60@3760.21,3685.9 3679.12,3685.9 3678.85,3685.63 3634.31,3685.63 3634.04,3685.9 3633.02,3685.9
GC9A01_BL: H10.2 U10.29 | length 409.4
  Top Layer w10: U10.29@4212.95,3843.38 4289.61,3843.38 v1(4301.18,3854.95)
  Bottom Layer w10: v1(4301.18,3854.95) 4511.73,3854.95 v1(4586.58,3929.8)
GC9A01_CS: H10.8 U10.26 | length 437.6
  Top Layer w10: U10.26@4212.95,3784.33 4265.5,3784.33 4274.41,3775.43 4325.2,3775.43 v1(4325.59,3775.03)
  Bottom Layer w10: v1(4325.59,3775.03) 4441.35,3775.03 v1(4586.58,3629.8)
GC9A01_DC: H10.6 U10.27 | length 404.4
  Top Layer w10: U10.27@4212.95,3804.01 4295.52,3804.01 v1(4298.82,3800.71)
  Bottom Layer w10: v1(4298.82,3800.71) 4515.67,3800.71 v1(4586.58,3729.8)
GC9A01_RST: H10.4 U10.28 | length 376.2
  Top Layer w10: U10.28@4212.95,3823.7 4323.47,3823.7 v1(4325.59,3825.82)
  Bottom Layer w10: v1(4325.59,3825.82) 4582.6,3825.82 v1(4586.58,3829.8)
GND: BTN1.1 BTN1.3 BTN2.1 BTN2.3 BTN3.1 BTN3.3 C1.2 C2.2 C3.2 C4.2 C5.2 C6.2 C7.2 C8.2 C9.2 C10.2 C11.2 C12.1 C13.1 C14.1 C15.2 C16.2 C17.2 C18.2 C19.2 C20.1 C21.2 C22.2 C23.2 CN1.7 D1.2 H9.1 H10.3 LEDG1.1 R3.1 R4.2 R6.1 R9.2 R27.1 U4.5 U5.3 U5.7 U5.11 U8.6 U8.10 U10.12 U10.18 U10.31 U10.47 U10.63 U12.9 U12.18 U12.19 USB1.5 USB1.6 X2.2 | length 1061
  Top Layer w10: v1(4035.43,3601.41) 4055.48,3581.36 U10.12@4055.48,3528.43 ; U10.18@4212.95,3626.85 4280.46,3626.85 C5.2
  Top Layer w11.81: U5.3 U5.11 3572.6,4053.91 U5.7 ; v1(3788.39,4135.31) 3798.82,4124.89 3798.82,4082.12 3859.06,4021.88 3859.06,3981.33 U10.47 ; U10.31@4212.95,3882.75 4213.1,3882.91 4255.12,3882.91 4276.38,3904.17 4276.38,3954.56 4301.74,3979.92 C3.2
  Top Layer w13.78: USB1.6@3444.68,3617.28 3444.68,3671.42 USB1.5 ; U10.63@3760.21,3626.85 v1(3824.8,3626.85)
  Bottom Layer w10: U12.18 U12.19 U12.9
  Bottom Layer w11.81: U12.9 3891.73,3824.25 3902.21,3834.72 3902.64,3834.72 3914.06,3846.14 v6(3916.35,3846.14)
  other v1: 4169.69,3130.94 3731.5,3164.8 3619.29,3334.88 4370.87,3383.7 3358.47,3522.07 4089.76,3688.42 3663.48,3727.93 3315.21,3739.06 4090.95,3792.75 3438.38,3861.38 4091.73,3877.79 3819.54,3881.66 4385.57,3900.4 4470.08,4002.99 3532.29,4016.37 3576.69,4026.19 3375.99,4051.8 3577.95,4059.28 4287.95,4139.52 4222.44,4359.28 3683.47,4364.01
MINUS_BTN: R13.2 U10.10 | length 367
  Top Layer w10: U10.10@4016.11,3528.43 4016.95,3527.6 4016.95,3480.53 4024.02,3473.46 4300.62,3473.46 R13.2
OSC32_IN: C18.1 U10.3 X1.1 | length 279.9
  Top Layer w11.81: C18.1@3744.49,3357.71 3750.33,3351.87 3823.05,3351.87 3879.14,3407.96 U10.3@3879.14,3527.61
OSC32_OUT: C19.1 U10.4 X1.2 | length 291.8
  Top Layer w11.81: U10.4@3898.82,3527.61 3898.82,3406.14 3923.44,3381.52 3923.44,3274.02 C19.1@3903.63,3254.21
OSC_25M: R8.2 U10.5 | length 242.4
  Top Layer w11.81: U10.5 3918.5,3460.08 3989.76,3388.81 R8.2
PLUS_BTN: R15.2 U10.8 | length 535.9
  Top Layer w10: R15.2 3645.06,3493.62 3645.06,3538.8 3685.57,3579.31 3802.96,3579.31 3822.7,3599.05 3955.12,3599.05 3976.74,3577.43 U10.8@3976.74,3528.43
RESET#: C4.1 R12.2 R17.1 U10.7 | length 495.7
  Top Layer w10: v1(3695.09,3556.32) 3695.09,3545.95 R12.2 ; C4.1 3731.24,3441.9 R12.2 ; U10.7@3957.05,3528.43 3957.05,3573.34 3947.05,3583.34 3826.81,3583.34 3753.27,3509.8 R12.2
  Bottom Layer w10: R17.1 3675.8,3575.61 v1(3695.09,3556.32)
SDIO1_CLK: U10.53 U12.6 | length 132
  Top Layer w10: U10.53@3760.21,3823.7 3801.31,3823.7 v2(3819.14,3805.88)
  Bottom Layer w10: v2(3819.14,3805.88) 3859.43,3765.58 U12.6
SDIO1_CMD: U10.54 U12.5 | length 130
  Top Layer w10: U10.54 3798.7,3803.77 3819.14,3783.34 v2(3819.14,3782.33)
  Bottom Layer w10: v2(3819.14,3782.33) 3851.64,3749.83 U12.5
SDIO1_D0: U10.34 U12.7 | length 376.7
  Top Layer w10: v3(3867.31,3781.41) 3867.31,3822.26 3908.98,3863.94 3923.75,3863.94 3951.51,3891.7 3996.62,3891.7 4035.49,3930.58 4102.67,3930.58 4115.35,3943.26 U10.34
SDIO1_D1: U10.39 U12.8 | length 262.6
  Top Layer w10: v2(3986.65,3925.25) 3991.98,3930.58 4004.24,3930.58 4016.93,3943.27 U10.39
  Bottom Layer w10: U12.8 3868.11,3823.72 3969.64,3925.25 v2(3986.65,3925.25)
SDIO1_D2: U10.51 U12.3 | length 227.5
  Bottom Layer w10: v2(3769.96,3862.77) 3759.96,3852.77 3759.96,3768.22 3809.84,3718.34 U12.3
SDIO1_D3: U10.52 U12.4 | length 192.6
  Top Layer w10: U10.52 v2(3790.55,3843.14)
  Bottom Layer w10: v2(3790.55,3843.14) 3803.31,3830.39 3803.31,3761.49 3830.71,3734.09 U12.4
SET_BTN: R14.2 U10.9 | length 316.8
  Top Layer w10: v1(3967.29,3452.84) 3996.85,3482.4 3996.85,3528 U10.9@3996.42,3528.43
  Bottom Layer w10: v1(3967.29,3452.84) 3967.29,3244.95 v1(3982.09,3230.15)
SPI1_MOSI: H10.5 U10.23 | length 275.5
  Top Layer w11.81: U10.23@4212.95,3725.27 4482.05,3725.27 H10.5
SPI1_SCK: H10.7 U10.21 | length 296.9
  Top Layer w11.81: U10.21@4212.95,3685.9 4430.48,3685.9 H10.7
TCK/SWCLK: R18.1 U10.49 | length 371
  Top Layer w10: v1(3692.91,3902.59) 3693.06,3902.44 U10.49@3760.21,3902.44
  Bottom Layer w10: R18.1 3652.18,3706.72 3624.38,3734.51 3624.38,3884.33 3642.64,3902.59 v1(3692.91,3902.59)
TDO/SWO: R20.1 U10.55 | length 156.1
  Top Layer w10: v1(3652.19,3864.51) 3652.19,3840.57 3709.45,3783.3 3759.18,3783.3 U10.55@3760.21,3784.33
TMS/SWDIO: R19.1 U10.45 | length 344.9
  Top Layer w10: U10.45@3898,3981.17 U10.45@3898.87,3981.17
  Bottom Layer w10: R19.1 3651.24,3784.93 3847.41,3981.11 v2(3898.93,3981.11)
USD_DETECT: U8.9 U10.44 U12.1 | length 1038.6
  Top Layer w10: v2(3867.68,3685.2) 3834.96,3717.92 3834.96,3858.9 3918.5,3942.44 U10.44
  Bottom Layer w10: v2(3867.68,3685.2) 3872.88,3680 3872.88,3579.76 4008.68,3443.96 4008.68,3424.34 4044.9,3388.11 4089.44,3388.11 4089.83,3388.5 4190.56,3388.5 U8.9
VBAT: C13.2 C15.1 C16.1 H9.2 R1.2 R2.1 R5.1 R11.2 U4.2 U5.10 | length 969.4
  Top Layer w10: U5.10@3512.99,4117.84 U5.10 ; v1(4086.11,4149.72) 4096.58,4160.2 R1.2
  Top Layer w11.81: U5.10@3512.99,4117.84 3512.99,4199.61 ; C15.1 3512.99,4199.61 ; R2.1 4262.3,4204.43 R11.2 ; R2.1@4163.39,4205.14 R1.2 4095.59,4206.13 4031.1,4206.13 4030.11,4205.14 3974.79,4205.14 C16.1 3971.58,4210.54 3947.32,4234.8 3791.58,4234.8 H9.2 3776.92,4229.46 R5.1 3665.12,4230.93 3544.31,4230.93 3512.99,4199.61
VCAP: C3.1 C10.1 U10.30 U10.46 | length 875.9
  Top Layer w11.81: U10.46 3879.13,4027.39 3944.88,4093.14 4283.07,4093.14 4396.58,3979.63 C10.1 4344.14,3924.8 C3.1 4319.02,3917.28 4264.81,3863.07 U10.30@4212.95,3863.07
VDDA: C11.1 C12.2 U10.13 | length 340.9
  Top Layer w11.81: v1(4075.04,3601.46) 4075.99,3600.51 U10.13@4075.99,3528.97
  Bottom Layer w11.81: v1(4075.04,3601.46) 4075.04,3422.72 C11.1 4144.73,3414.84 C12.2
pads on no net: BTN1.6 BTN2.6 BTN3.6 C1.1 C2.1 C5.1 C6.1 C7.1 C8.1 C9.1 C17.1 C20.2 C22.1 C23.1 H10.1 R7.2 R12.1 R16.1 U4.3 U4.4 U5.5 U5.6 U8.4 U8.11 U8.12 U8.13 U8.14 U8.15 U10.1 U10.2 U10.6 U10.11 U10.15 U10.17 U10.19 U10.20 U10.22 U10.24 U10.25 U10.32 U10.33 U10.35 U10.36 U10.37 U10.38 U10.40 U10.41 U10.42 U10.43 U10.48 U10.50 U10.56 U10.57 U10.58 U10.59 U10.61 U10.62 U10.64 U12.2 U12.16 U12.17 USB1.2 USB1.3 USB1.4 X2.4
copper on no net: | length 1159.7
  Top Layer w10: v1(4088.19,3172.28) 4098.3,3182.39 4157.35,3182.39 4157.35,3276.74 4156.3,3277.79
  Top Layer w11.81: v1(3814.41,4013.61) 3839.76,3988.26 3839.76,3980.93 ; 4212.95,3902.44 4221.58,3911.07 v1(4221.58,3992.24)
  Top Layer w13.78: 3656.58,3657.24 3656.58,3641.77 v1(3691.97,3606.38) 3692.76,3607.16 3760.21,3607.16 ; v1(3809.02,3526.85) 3817.53,3518.34 3828.85,3518.34 3838.94,3528.43 ; v1(3911.58,4151.94) 3911.58,4206.94 ; 4212.95,3646.53 4213.51,3647.09 v1(4316.58,3647.09) ; v1(4446.06,3534.88) 4446.14,3534.8 4529.89,3534.8 4530.67,3534.02
  Bottom Layer w10: v4(3894.49,3646.15) 3894.49,3647.49 3915.35,3668.35 3915.35,3686.84 3915.35,3702.59
  Bottom Layer w11.81: v1(3856.89,3913.35) 3872.25,3897.99 3872.25,3881.06
  Bottom Layer w13.78: 3636.24,3474.8 3671.24,3509.8 v1(3671.92,3509.8) 3689.02,3509.8 3724.02,3474.8 3719.02,3469.8 3719.02,3394.8 ; v1(3968,4149.72) 3968.2,4149.93 4026.85,4149.93 4027.05,4149.72 ; 4250.05,3229.9 4250.05,3192.71 v1(4277.95,3164.8)
  other v1: 4317.25,3249.57 3980.66,3753.89 4486.58,3929.8 3852.17,4079.58

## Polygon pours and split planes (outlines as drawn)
GND on Top Layer (solid, remove dead copper): 4695.68,3754.8 ccw(c3986.58,3753.74) 3277.48,3754.8 ccw(c3986.58,3755.87)
GND on Bottom Layer (solid, remove dead copper, pour order 2): 4695.65,3754.39 ccw(c3985.19,3754.39) 3274.73,3754.39 ccw(c3985.19,3754.39)
GND on Inner1 (solid, remove dead copper): 4695.08,3754.79 ccw(c3985.97,3754.79) 3276.87,3754.79 ccw(c3985.97,3754.79)
no net on Inner2 (solid, remove dead copper): 4707.1,3748.62 ccw(c3998,3746.87) 3288.9,3748.62 ccw(c3998,3750.37)

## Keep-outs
Inner1:
  region: 3756.32,3456.45 3685.56,3385.69 3685.56,3316.9 3735.69,3266.77 3815.74,3225.03 3917.68,3225.03 3987.4,3281.33 3987.4,3414.4 3945.36,3456.45
  region: 4040.95,3450.01 4040.95,3269.13 4099.21,3210.86 4225.2,3210.86 4274.41,3260.07 4274.41,3364.34 4225.98,3412.77 4225.98,3466.77 4057.7,3466.77
Board Outline Layer:
  circle w10: c3985.98,3754.79 r720.17

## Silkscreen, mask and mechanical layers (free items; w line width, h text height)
Bottom Silkscreen Layer:
  text "Company: UnNatural /  Designed by: Andrea Fato /  Date: 18/09/2024" at 3944.88,3286.85 h31.5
